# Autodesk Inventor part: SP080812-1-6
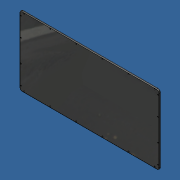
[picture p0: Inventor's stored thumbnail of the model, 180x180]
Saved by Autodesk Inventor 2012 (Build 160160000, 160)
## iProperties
Created: 2012-08
Part Number: SP080812-1-6
Material: UHMW, Black
Document SubType Name: Modeling
Designer: Administrator
Mass: 13807.9 g
Surface Area: 23697.3 cm^2
Volume: 14689.2 cm^3
Density: 0.94 g/cm^3
Author: Administrator
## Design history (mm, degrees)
sketch "Sketch1"
  geometry: L1 (-10.9, 351)-(-10.9, -351) reference; L2 (19.1, 381)-(1483.1, 381) reference; L3 (1483.1, -381)-(19.1, -381) reference; L4 (1513.1, -351)-(1513.1, 351) reference; L5 (-10.9, 381)-(1513.1, 381); L6 (1513.1, 381)-(1513.1, -381); L7 (1513.1, -381)-(-10.9, -381); L8 (-10.9, -381)-(-10.9, 381); 1 further point
  constraints: 8 end point, 4 collinear, 2 parallel, 1 horizontal, 1 perpendicular
extrude "Extrusion1" new body sketch "Sketch1" distance "d0" = 12.7; taper "d1" = 0 deg
fillet "Fillet1" dims "d2" = 27.5
fillet "Fillet2" dims "d3" = 6.35
sketch "Sketch2"
  geometry: L1 (16.6, -381)-(1485.6, -381) reference; L2 (-10.9, 353.5)-(-10.9, -353.5) reference; L3 (1485.6, 381)-(16.6, 381) reference; L4 (1513.1, -353.5)-(1513.1, 353.5) reference; L5 (4.1, 366)-(1498.1, 366); L6 (1498.1, 366)-(1498.1, -366); L7 (1498.1, -366)-(4.1, -366); L8 (4.1, -366)-(4.1, 366); 21 further points
  constraints: 20 point on line, 8 end point, 2 parallel, 1 horizontal, 1 perpendicular
  dimensions: "d4" = 15 distance between parallel lines of L5 L3; "d5" = 15 distance between parallel lines of L4 L6 (= d4); "d6" = 15 distance between parallel lines of L7 L1 (= d5); "d7" = 15 distance between parallel lines of L8 L2 (= d4); "d8" = 50.8 distance from line of point (1498.1, 330.2) L3; "d9" = 50.8 distance from line of L4 point (1462.3, 366) (= d8); "d10" = 50.8 distance from line of point (1462.3, -366) L4 (= d8); "d11" = 50.8 distance from line of point (1498.1, -330.2) L1 (= d10); "d12" = 50.8 distance from line of point (39.9, -366) L2; "d13" = 50.8 distance from line of point (4.1, -330.2) L1; "d14" = 50.8 distance from line of point (39.9, 366) L2; "d15" = 50.8 distance from line of point (4.1, 330.2) L3; "d16" = 1422.4 distance of point (39.9, 366) point (1462.3, 366) (derived); "d17" = 284.48 distance of point (324.38, 366) point (39.9, 366) (= 0.2 x d16); "d18" = 284.48 distance of point (608.86, 366) point (324.38, 366) (= d17); "d19" = 284.48 distance of point (893.34, 366) point (608.86, 366) (= d18); "d20" = 284.48 distance of point (1177.82, 366) point (893.34, 366) (= d19); "d21" = 284.48 distance of point (324.38, -366) point (39.9, -366) (= d17); "d22" = 284.48 distance of point (608.86, -366) point (324.38, -366) (= d21); "d23" = 284.48 distance of point (893.34, -366) point (608.86, -366) (= d22); "d24" = 284.48 distance of point (1177.82, -366) point (893.34, -366) (= d23); "d25" = 732 distance of point (1462.3, -366) point (1462.3, 366) (derived); "d26" = 244 vertical distance of point (1498.1, 122) point (1462.3, 366) (= 0.333333 x d25); "d27" = 244 distance of point (1498.1, -122) point (1498.1, 122) (= d26); "d28" = 732 distance of point (39.9, -366) point (39.9, 366) (derived); "d29" = 244 vertical distance of point (4.1, 122) point (39.9, 366) (= 0.333333 x d28); "d30" = 244 distance of point (4.1, -122) point (4.1, 122) (= d29)
hole "Hole1" sketch "Sketch2" at (39.9, 366), (1462.3, 366), (1177.82, 366), (893.34, 366), (608.86, 366), (324.38, 366), (1462.3, -366), (39.9, -366), (324.38, -366), (608.86, -366), (893.34, -366), (1177.82, -366)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 diameter "d31" = 6.5; stored, may be unused: countersink angle "d35" = 90 deg, drill point angle "d37" = 118 deg; dims "d32" = 12.7, "d33" = 13.5, "d34" = 6.35, "d36" = 19.05
body "Solid1"
node "Reference1"
node "Reference2"
node "Reference3"
node "Reference4"
